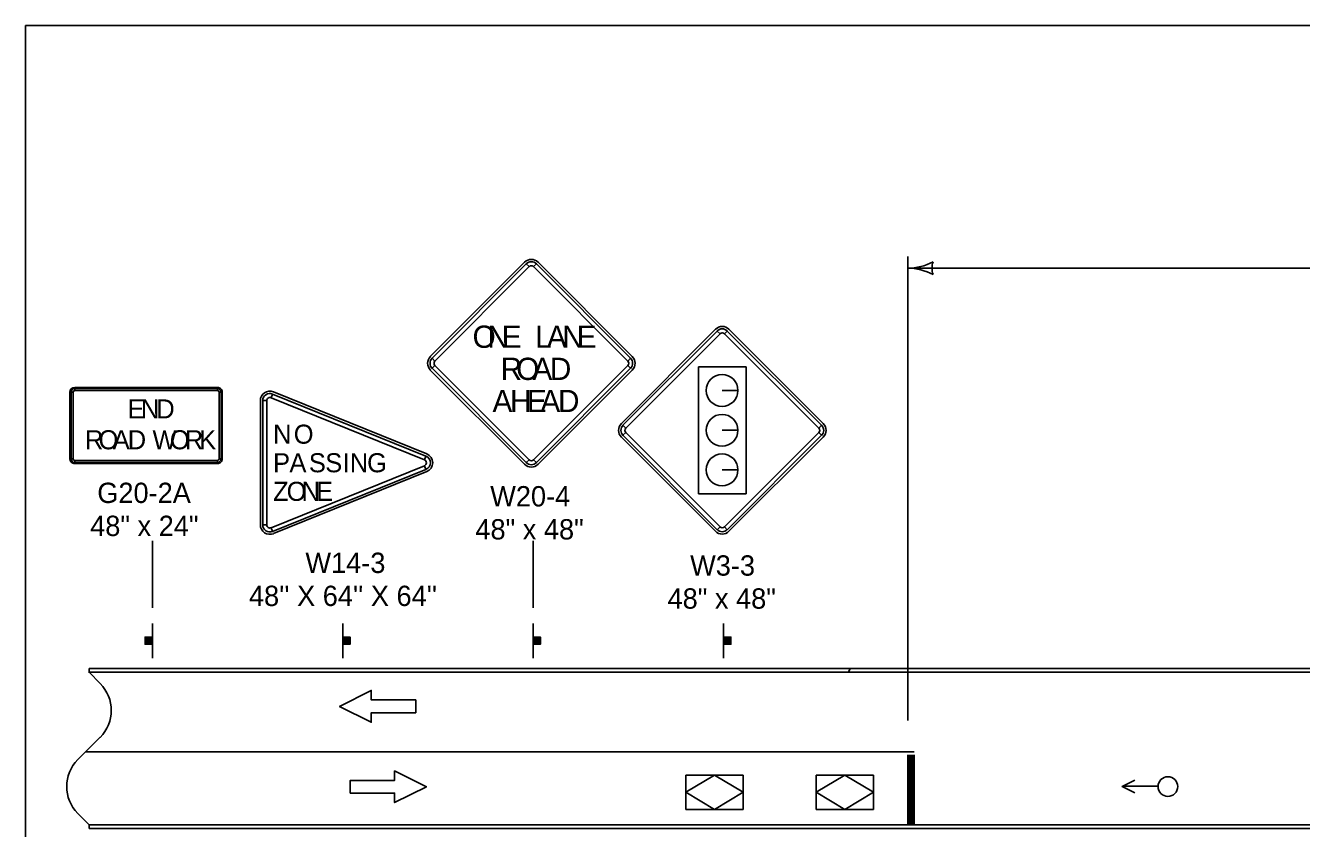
# Model space of a CAD drawing. Extents: x -2134934 to -2119606, y -2139046 to -2137036.
# Drawn here: x -2134934 to -2133929, y -2137668 to -2137036 of the extents above; entities that cross this region are included whole.
import ezdxf

# ---------------------------------------------------------------- set-up
doc = ezdxf.new("R2010")
doc.units = 0
for name, color, linetype in [('Default', 7, 'Continuous'), ('dsnCellElements', 7, 'Continuous'), ('dsnStdLabel', 7, 'Continuous'), ('dsnStdLineWork', 7, 'Continuous'), ('Level 2', 7, 'Continuous'), ('Level 4', 7, 'Continuous')]:
    doc.layers.add(name, color=color, linetype=linetype)

msp = doc.modelspace()

# ---------------------------------------------------------------- linework, layer by layer
at = {"layer": 'Default'}
msp.add_lwpolyline([(-2134934.4, -2137035.9), (-2131799.4, -2137035.9), (-2131799.4, -2139045.9), (-2134934.4, -2139045.9)], close=True, dxfattribs=at)
at = {"layer": 'dsnCellElements'}
for centre, radius, start, end in [((-2134239.4, -2137184.5), 42.5, 270, 298.0725), ((-2134203.8, -2137227), 16.4, 162.2666, 197.7334), ((-2134239.4, -2137269.5), 42.5, 61.9275, 90)]:
    msp.add_arc(centre, radius, start, end, dxfattribs=at)
at = {"layer": 'dsnStdLabel'}
for p, q in [((-2134541.2, -2137222.3), (-2134615.5, -2137296.6)), ((-2134456.4, -2137296.6), (-2134530.6, -2137222.3)), ((-2134539.9, -2137223.6), (-2134537.7, -2137225.8)), ((-2134534.1, -2137225.8), (-2134531.9, -2137223.6)), ((-2134390.8, -2137275.1), (-2134465, -2137349.4)), ((-2134389.4, -2137276.5), (-2134387.2, -2137278.7)), ((-2134383.7, -2137278.7), (-2134381.5, -2137276.5)), ((-2134305.9, -2137349.4), (-2134380.2, -2137275.1)), ((-2134611.9, -2137300.1), (-2134614.1, -2137297.9)), ((-2134614.1, -2137305.8), (-2134611.9, -2137303.6)), ((-2134457.7, -2137297.9), (-2134459.9, -2137300.1)), ((-2134459.9, -2137303.6), (-2134457.7, -2137305.8)), ((-2134615.5, -2137307.2), (-2134541.2, -2137381.4)), ((-2134530.6, -2137381.4), (-2134456.4, -2137307.2)), ((-2134783.2, -2137320.9), (-2134895.7, -2137320.9)), ((-2134895.7, -2137323.4), (-2134895.7, -2137321.8)), ((-2134783.2, -2137321.8), (-2134783.2, -2137323.4)), ((-2134373.1, -2137323.3), (-2134385.6, -2137323.3)), ((-2134385.6, -2137323.3), (-2134373.1, -2137323.3)), ((-2134899.4, -2137324.6), (-2134899.4, -2137377.1)), ((-2134898.5, -2137324.6), (-2134896.9, -2137324.6)), ((-2134781.9, -2137324.6), (-2134780.4, -2137324.6)), ((-2134779.4, -2137377.1), (-2134779.4, -2137324.6)), ((-2134749.4, -2137331.3), (-2134749.4, -2137429.1)), ((-2134747.5, -2137331.3), (-2134744.4, -2137331.3)), ((-2134741, -2137329), (-2134739.8, -2137326.1)), ((-2134618.3, -2137373.2), (-2134739.1, -2137324.4)), ((-2134461.5, -2137352.9), (-2134463.7, -2137350.7)), ((-2134307.2, -2137350.7), (-2134309.5, -2137352.9)), ((-2134465, -2137360), (-2134390.8, -2137434.2)), ((-2134463.7, -2137358.6), (-2134461.5, -2137356.4)), ((-2134373.1, -2137354.6), (-2134385.6, -2137354.6)), ((-2134385.6, -2137354.6), (-2134373.1, -2137354.6)), ((-2134380.2, -2137434.2), (-2134305.9, -2137360)), ((-2134309.5, -2137356.4), (-2134307.2, -2137358.6)), ((-2134896.9, -2137377.1), (-2134898.5, -2137377.1)), ((-2134895.7, -2137379.9), (-2134895.7, -2137378.4)), ((-2134895.7, -2137380.9), (-2134783.2, -2137380.9)), ((-2134783.2, -2137378.4), (-2134783.2, -2137379.9)), ((-2134780.4, -2137377.1), (-2134781.9, -2137377.1)), ((-2134619, -2137375), (-2134620.1, -2137377.9)), ((-2134620.1, -2137382.5), (-2134619, -2137385.4)), ((-2134537.7, -2137377.9), (-2134539.9, -2137380.1)), ((-2134531.9, -2137380.1), (-2134534.1, -2137377.9)), ((-2134739.1, -2137436), (-2134618.3, -2137387.2)), ((-2134373.1, -2137385.8), (-2134385.6, -2137385.8)), ((-2134385.6, -2137385.8), (-2134373.1, -2137385.8)), ((-2134744.4, -2137429.1), (-2134747.5, -2137429.1)), ((-2134739.8, -2137434.3), (-2134741, -2137431.4)), ((-2134387.2, -2137430.7), (-2134389.4, -2137432.9)), ((-2134381.5, -2137432.9), (-2134383.7, -2137430.7))]:
    msp.add_line(p, q, dxfattribs=at)
for points in [[(-2134539.9, -2137223.6), (-2134614.1, -2137297.9), (-2134611.9, -2137300.1), (-2134537.7, -2137225.8), (-2134539.9, -2137223.6)], [(-2134457.7, -2137297.9), (-2134531.9, -2137223.6), (-2134534.1, -2137225.8), (-2134459.9, -2137300.1), (-2134457.7, -2137297.9)], [(-2134389.4, -2137276.5), (-2134463.7, -2137350.7), (-2134461.5, -2137352.9), (-2134387.2, -2137278.7), (-2134389.4, -2137276.5)], [(-2134307.2, -2137350.7), (-2134381.5, -2137276.5), (-2134383.7, -2137278.7), (-2134309.5, -2137352.9), (-2134307.2, -2137350.7)], [(-2134614.1, -2137305.8), (-2134539.9, -2137380.1), (-2134537.7, -2137377.9), (-2134611.9, -2137303.6), (-2134614.1, -2137305.8)], [(-2134531.9, -2137380.1), (-2134457.7, -2137305.8), (-2134459.9, -2137303.6), (-2134534.1, -2137377.9), (-2134531.9, -2137380.1)], [(-2134366.7, -2137304.7), (-2134404.2, -2137304.7), (-2134404.2, -2137404.6), (-2134366.7, -2137404.6), (-2134366.7, -2137304.7)], [(-2134783.2, -2137321.8), (-2134895.7, -2137321.8), (-2134895.7, -2137323.4), (-2134783.2, -2137323.4), (-2134783.2, -2137321.8)], [(-2134898.5, -2137324.6), (-2134898.5, -2137377.1), (-2134896.9, -2137377.1), (-2134896.9, -2137324.6), (-2134898.5, -2137324.6)], [(-2134780.4, -2137377.1), (-2134780.4, -2137324.6), (-2134781.9, -2137324.6), (-2134781.9, -2137377.1), (-2134780.4, -2137377.1)], [(-2134747.5, -2137331.3), (-2134747.5, -2137429.1), (-2134744.4, -2137429.1), (-2134744.4, -2137331.3), (-2134747.5, -2137331.3)], [(-2134619, -2137375), (-2134739.8, -2137326.1), (-2134741, -2137329), (-2134620.1, -2137377.9), (-2134619, -2137375)], [(-2134463.7, -2137358.6), (-2134389.4, -2137432.9), (-2134387.2, -2137430.7), (-2134461.5, -2137356.4), (-2134463.7, -2137358.6)], [(-2134381.5, -2137432.9), (-2134307.2, -2137358.6), (-2134309.5, -2137356.4), (-2134383.7, -2137430.7), (-2134381.5, -2137432.9)], [(-2134895.7, -2137379.9), (-2134783.2, -2137379.9), (-2134783.2, -2137378.4), (-2134895.7, -2137378.4), (-2134895.7, -2137379.9)], [(-2134739.8, -2137434.3), (-2134619, -2137385.4), (-2134620.1, -2137382.5), (-2134741, -2137431.4), (-2134739.8, -2137434.3)]]:
    msp.add_lwpolyline(points, close=True, dxfattribs=at)
for centre in [(-2134385.6, -2137323.3), (-2134385.6, -2137354.6), (-2134385.6, -2137385.8)]:
    msp.add_circle(centre, 12.5, dxfattribs=at)
for centre, radius, start, end in [((-2134535.9, -2137227.6), 7.5, 45, 134.9997), ((-2134535.9, -2137227.6), 5.62, 45, 134.9997), ((-2134535.9, -2137227.6), 2.5, 45, 134.9997), ((-2134385.5, -2137280.4), 7.5, 45, 134.9997), ((-2134385.5, -2137280.4), 5.62, 45, 134.9997), ((-2134385.5, -2137280.4), 2.5, 45, 134.9997), ((-2134610.1, -2137301.9), 7.5, 134.9997, 225), ((-2134610.1, -2137301.9), 5.62, 134.9997, 225), ((-2134610.1, -2137301.9), 2.5, 134.9997, 225), ((-2134461.7, -2137301.9), 2.5, 315.0002, 44.9998), ((-2134461.7, -2137301.9), 5.62, 315.0002, 44.9998), ((-2134461.7, -2137301.9), 7.5, 315.0002, 44.9998), ((-2134895.7, -2137324.6), 3.75, 90.0002, 179.9998), ((-2134895.7, -2137324.6), 2.81, 90.0002, 179.9998), ((-2134895.7, -2137324.6), 1.25, 90.0002, 179.9998), ((-2134783.2, -2137324.6), 3.75, 0, 90.0002), ((-2134783.2, -2137324.6), 2.81, 0, 90.0002), ((-2134783.2, -2137324.6), 1.25, 0, 90.0002), ((-2134741.9, -2137331.3), 7.5, 67.9757, 179.9998), ((-2134741.9, -2137331.3), 5.62, 67.9757, 179.9998), ((-2134741.9, -2137331.3), 2.5, 67.9757, 179.9998), ((-2134459.7, -2137354.7), 7.5, 134.9997, 225), ((-2134459.7, -2137354.7), 5.62, 134.9997, 225), ((-2134459.7, -2137354.7), 2.5, 134.9997, 225), ((-2134311.2, -2137354.7), 2.5, 315.0002, 44.9998), ((-2134311.2, -2137354.7), 5.62, 315.0002, 44.9998), ((-2134311.2, -2137354.7), 7.5, 315.0002, 44.9998), ((-2134621.1, -2137380.2), 7.5, 292.0246, 67.976), ((-2134895.7, -2137377.1), 3.75, 179.9998, 270.0001), ((-2134895.7, -2137377.1), 2.81, 179.9998, 270.0001), ((-2134895.7, -2137377.1), 1.25, 179.9998, 270.0001), ((-2134783.2, -2137377.1), 3.75, 270.0001, 0.0003), ((-2134783.2, -2137377.1), 2.81, 270.0001, 0.0003), ((-2134783.2, -2137377.1), 1.25, 270.0001, 0.0003), ((-2134621.1, -2137380.2), 2.5, 292.0246, 67.9754), ((-2134621.1, -2137380.2), 5.62, 292.0246, 67.9754), ((-2134535.9, -2137376.1), 7.5, 225, 315.0002), ((-2134535.9, -2137376.1), 5.62, 225, 315.0002), ((-2134535.9, -2137376.1), 2.5, 225, 315.0002), ((-2134741.9, -2137429.1), 7.5, 179.9998, 292.0246), ((-2134741.9, -2137429.1), 5.62, 179.9998, 292.0246), ((-2134741.9, -2137429.1), 2.5, 179.9998, 292.0246), ((-2134385.5, -2137428.9), 7.5, 225, 315.0002), ((-2134385.5, -2137428.9), 5.62, 225, 315.0002), ((-2134385.5, -2137428.9), 2.5, 225, 315.0002)]:
    msp.add_arc(centre, radius, start, end, dxfattribs=at)
at = {"layer": 'dsnStdLineWork'}
for p, q in [((-2134884.4, -2137542.2), (-2134884.4, -2137545.2)), ((-2134884.4, -2137542.2), (-2134884.4, -2137545.2)), ((-2134284.7, -2137542.2), (-2134884.4, -2137542.2)), ((-2134284.7, -2137542.2), (-2134285.9, -2137545.2)), ((-2134285.9, -2137545.2), (-2134284.7, -2137542.2)), ((-2134239.4, -2137542.2), (-2134284.7, -2137542.2)), ((-2133766.5, -2137542.2), (-2134239.4, -2137542.2)), ((-2134239.4, -2137542.2), (-2134239.4, -2137545.2)), ((-2134239.4, -2137545.2), (-2134239.4, -2137542.2)), ((-2134884.4, -2137545.2), (-2134285.9, -2137545.2)), ((-2134285.9, -2137545.2), (-2134239.4, -2137545.2)), ((-2134239.4, -2137545.2), (-2133764.3, -2137545.2)), ((-2134234.4, -2137607.7), (-2134886.9, -2137607.7)), ((-2134884.4, -2137665.2), (-2133384.4, -2137665.2)), ((-2134884.4, -2137665.2), (-2133384.4, -2137665.2)), ((-2134884.4, -2137668.2), (-2134884.4, -2137665.2)), ((-2134239.4, -2137665.2), (-2134884.4, -2137665.2)), ((-2134884.4, -2137665.2), (-2134884.4, -2137668.2)), ((-2134238.4, -2137665.2), (-2134239.4, -2137665.2)), ((-2134237.4, -2137665.2), (-2134238.4, -2137665.2)), ((-2134236.4, -2137665.2), (-2134237.4, -2137665.2)), ((-2133384.4, -2137665.2), (-2134234.4, -2137665.2)), ((-2134884.4, -2137668.2), (-2133384.4, -2137668.2)), ((-2134884.4, -2137668.2), (-2133384.4, -2137668.2))]:
    msp.add_line(p, q, dxfattribs=at)
for points in [[(-2134884.4, -2137542.2), (-2133574.4, -2137542.2)], [(-2134884.9, -2137545.2), (-2133574.9, -2137545.2)], [(-2134884.4, -2137545.2), (-2133574.4, -2137545.2)], [(-2134234.4, -2137665.2), (-2134235.4, -2137665.2), (-2134236.4, -2137665.2)]]:
    msp.add_lwpolyline(points, dxfattribs=at)
at = {"layer": 'Level 2'}
for p, q in [((-2134239.4, -2137583.2), (-2134239.4, -2137217.7)), ((-2134239.4, -2137227), (-2133580, -2137227)), ((-2134834.4, -2137494.5), (-2134834.4, -2137441.6)), ((-2134534.4, -2137494.5), (-2134534.4, -2137441.6)), ((-2134834.4, -2137506.7), (-2134834.4, -2137534.2)), ((-2134684.4, -2137506.7), (-2134684.4, -2137534.2)), ((-2134534.4, -2137506.7), (-2134534.4, -2137534.2)), ((-2134384.4, -2137506.7), (-2134384.4, -2137534.2)), ((-2134839.8, -2137517.5), (-2134839.8, -2137523.1)), ((-2134839.4, -2137523.1), (-2134839.4, -2137517.5)), ((-2134839.2, -2137517.5), (-2134839.2, -2137523.1)), ((-2134838.9, -2137523.1), (-2134838.9, -2137517.5)), ((-2134838.7, -2137517.5), (-2134838.7, -2137523.1)), ((-2134838.3, -2137523.1), (-2134838.2, -2137517.5)), ((-2134838, -2137517.5), (-2134838, -2137523.1)), ((-2134837.6, -2137523.1), (-2134837.6, -2137517.5)), ((-2134837.2, -2137517.5), (-2134837.2, -2137523.1)), ((-2134836.9, -2137523.1), (-2134836.9, -2137517.5)), ((-2134836.7, -2137517.5), (-2134836.7, -2137523.1)), ((-2134836.4, -2137523.1), (-2134836.4, -2137517.5)), ((-2134836.1, -2137517.5), (-2134836.1, -2137523.1)), ((-2134835.9, -2137523.1), (-2134835.9, -2137517.5)), ((-2134835.7, -2137517.5), (-2134835.7, -2137523.1)), ((-2134835.4, -2137523.1), (-2134835.4, -2137517.5)), ((-2134835.1, -2137517.5), (-2134835.1, -2137523.1)), ((-2134834.9, -2137523.1), (-2134834.9, -2137517.5)), ((-2134684, -2137523.1), (-2134684, -2137517.5)), ((-2134683.7, -2137517.5), (-2134683.7, -2137523.1)), ((-2134683.5, -2137523.1), (-2134683.5, -2137517.5)), ((-2134683.2, -2137517.5), (-2134683.2, -2137523.1)), ((-2134683, -2137523.1), (-2134683, -2137517.5)), ((-2134682.8, -2137517.5), (-2134682.8, -2137523.1)), ((-2134682.5, -2137523.1), (-2134682.5, -2137517.5)), ((-2134682.2, -2137517.5), (-2134682.2, -2137523.1)), ((-2134682, -2137523.1), (-2134682, -2137517.5)), ((-2134681.6, -2137517.5), (-2134681.6, -2137523.1)), ((-2134681.3, -2137523.1), (-2134681.3, -2137517.5)), ((-2134680.8, -2137517.5), (-2134680.8, -2137523.1)), ((-2134680.6, -2137523.1), (-2134680.6, -2137517.5)), ((-2134680.2, -2137517.5), (-2134680.2, -2137523.1)), ((-2134680, -2137523.1), (-2134680, -2137517.5)), ((-2134679.7, -2137517.5), (-2134679.7, -2137523.1)), ((-2134679.4, -2137523.1), (-2134679.4, -2137517.5)), ((-2134679.1, -2137517.5), (-2134679.1, -2137523.1)), ((-2134534, -2137523.1), (-2134534, -2137517.5)), ((-2134533.7, -2137517.5), (-2134533.7, -2137523.1)), ((-2134533.5, -2137523.1), (-2134533.5, -2137517.5)), ((-2134533.2, -2137517.5), (-2134533.2, -2137523.1)), ((-2134533, -2137523.1), (-2134533, -2137517.5)), ((-2134532.8, -2137517.5), (-2134532.8, -2137523.1)), ((-2134532.5, -2137523.1), (-2134532.5, -2137517.5)), ((-2134532.2, -2137517.5), (-2134532.2, -2137523.1)), ((-2134532, -2137523.1), (-2134532, -2137517.5)), ((-2134531.6, -2137517.5), (-2134531.6, -2137523.1)), ((-2134531.3, -2137523.1), (-2134531.3, -2137517.5)), ((-2134530.8, -2137517.5), (-2134530.8, -2137523.1)), ((-2134530.6, -2137523.1), (-2134530.6, -2137517.5)), ((-2134530.2, -2137517.5), (-2134530.2, -2137523.1)), ((-2134530, -2137523.1), (-2134530, -2137517.5)), ((-2134529.7, -2137517.5), (-2134529.7, -2137523.1)), ((-2134529.4, -2137523.1), (-2134529.4, -2137517.5)), ((-2134529.1, -2137517.5), (-2134529.1, -2137523.1)), ((-2134384, -2137523.1), (-2134384, -2137517.5)), ((-2134383.7, -2137517.5), (-2134383.7, -2137523.1)), ((-2134383.5, -2137523.1), (-2134383.5, -2137517.5)), ((-2134383.2, -2137517.5), (-2134383.2, -2137523.1)), ((-2134383, -2137523.1), (-2134383, -2137517.5)), ((-2134382.8, -2137517.5), (-2134382.8, -2137523.1)), ((-2134382.5, -2137523.1), (-2134382.5, -2137517.5)), ((-2134382.2, -2137517.5), (-2134382.2, -2137523.1)), ((-2134382, -2137523.1), (-2134382, -2137517.5)), ((-2134381.6, -2137517.5), (-2134381.6, -2137523.1)), ((-2134381.3, -2137523.1), (-2134381.3, -2137517.5)), ((-2134380.8, -2137517.5), (-2134380.8, -2137523.1)), ((-2134380.6, -2137523.1), (-2134380.6, -2137517.5)), ((-2134380.2, -2137517.5), (-2134380.2, -2137523.1)), ((-2134380, -2137523.1), (-2134380, -2137517.5)), ((-2134379.7, -2137517.5), (-2134379.7, -2137523.1)), ((-2134379.4, -2137523.1), (-2134379.4, -2137517.5)), ((-2134379.1, -2137517.5), (-2134379.1, -2137523.1)), ((-2134875.7, -2137553.9), (-2134884.4, -2137545.2)), ((-2133574.4, -2137545.2), (-2134884.4, -2137545.2)), ((-2134884.4, -2137545.2), (-2134875.7, -2137553.9)), ((-2134893.2, -2137613.9), (-2134875.7, -2137596.4)), ((-2134875.7, -2137596.4), (-2134893.2, -2137613.9)), ((-2134239.4, -2137665.2), (-2134239.4, -2137610.2)), ((-2134238.4, -2137665.2), (-2134238.4, -2137610.2)), ((-2134237.4, -2137665.2), (-2134237.4, -2137610.2)), ((-2134236.4, -2137665.2), (-2134236.4, -2137610.2)), ((-2134235.4, -2137665.2), (-2134235.4, -2137610.2)), ((-2134234.4, -2137665.2), (-2134234.4, -2137610.2)), ((-2134414.1, -2137653.1), (-2134414.1, -2137626.1)), ((-2134414.1, -2137626.1), (-2134369.1, -2137626.1)), ((-2134414.1, -2137653.1), (-2134414.1, -2137626.1)), ((-2134414.1, -2137626.1), (-2134369.1, -2137626.1)), ((-2134369.1, -2137626.1), (-2134414.1, -2137626.1)), ((-2134414.1, -2137626.1), (-2134414.1, -2137653.1)), ((-2134369.1, -2137653.1), (-2134369.1, -2137626.1)), ((-2134369.1, -2137626.1), (-2134369.1, -2137653.1)), ((-2134369.1, -2137653.1), (-2134369.1, -2137626.1)), ((-2134311.4, -2137653.1), (-2134311.4, -2137626.1)), ((-2134311.4, -2137626.1), (-2134266.4, -2137626.1)), ((-2134311.4, -2137653.1), (-2134311.4, -2137626.1)), ((-2134311.4, -2137626.1), (-2134266.4, -2137626.1)), ((-2134266.4, -2137626.1), (-2134311.4, -2137626.1)), ((-2134311.4, -2137626.1), (-2134311.4, -2137653.1)), ((-2134266.4, -2137653.1), (-2134266.4, -2137626.1)), ((-2134266.4, -2137626.1), (-2134266.4, -2137653.1)), ((-2134266.4, -2137653.1), (-2134266.4, -2137626.1)), ((-2134042.2, -2137634.8), (-2134070.1, -2137634.8)), ((-2134414.1, -2137653.1), (-2134369.1, -2137653.1)), ((-2134369.1, -2137653.1), (-2134414.1, -2137653.1)), ((-2134414.1, -2137653.1), (-2134369.1, -2137653.1)), ((-2134311.4, -2137653.1), (-2134266.4, -2137653.1)), ((-2134266.4, -2137653.1), (-2134311.4, -2137653.1)), ((-2134311.4, -2137653.1), (-2134266.4, -2137653.1)), ((-2134884.4, -2137665.2), (-2134893.2, -2137656.4)), ((-2134893.2, -2137656.4), (-2134884.4, -2137665.2)), ((-2134884.4, -2137665.2), (-2133384.4, -2137665.2))]:
    msp.add_line(p, q, dxfattribs=at)
for points in [[(-2134834.5, -2137523.1), (-2134834.5, -2137517.5), (-2134840.2, -2137517.5), (-2134840.2, -2137523.1)], [(-2134684.3, -2137523.1), (-2134684.3, -2137517.5), (-2134678.7, -2137517.5), (-2134678.7, -2137523.1)], [(-2134534.3, -2137523.1), (-2134534.3, -2137517.5), (-2134528.7, -2137517.5), (-2134528.7, -2137523.1)], [(-2134384.3, -2137523.1), (-2134384.3, -2137517.5), (-2134378.7, -2137517.5), (-2134378.7, -2137523.1)], [(-2134627, -2137577), (-2134627, -2137567), (-2134662, -2137567), (-2134662, -2137559.5), (-2134687, -2137572), (-2134662, -2137584.5), (-2134662, -2137577)], [(-2134678.6, -2137630.3), (-2134678.6, -2137640.3), (-2134643.6, -2137640.3), (-2134643.6, -2137647.8), (-2134618.6, -2137635.3), (-2134643.6, -2137622.8), (-2134643.6, -2137630.3)]]:
    msp.add_lwpolyline(points, close=True, dxfattribs=at)
for points in [[(-2134662, -2137577), (-2134662, -2137584.5), (-2134687, -2137572), (-2134662, -2137559.5), (-2134662, -2137567), (-2134627, -2137567), (-2134627, -2137577), (-2134662, -2137577)], [(-2134643.6, -2137630.3), (-2134643.6, -2137622.8), (-2134618.6, -2137635.3), (-2134643.6, -2137647.8), (-2134643.6, -2137640.3), (-2134678.6, -2137640.3), (-2134678.6, -2137630.3), (-2134643.6, -2137630.3)], [(-2134060.5, -2137630), (-2134070.5, -2137635), (-2134060.5, -2137640)]]:
    msp.add_lwpolyline(points, dxfattribs=at)
msp.add_circle((-2134034.4, -2137635.2), 7.74, dxfattribs=at)
for centre, start, end in [((-2134896.9, -2137575.2), 315, 45), ((-2134896.9, -2137575.2), 315, 45), ((-2134872, -2137635.2), 135, 225), ((-2134872, -2137635.2), 135, 225)]:
    msp.add_arc(centre, 30, start, end, dxfattribs=at)
at = {"layer": 'Level 4'}
for points in [[(-2134414.1, -2137639.6), (-2134391.6, -2137626.1), (-2134369.1, -2137639.6), (-2134391.6, -2137653.1)], [(-2134311.4, -2137639.6), (-2134288.9, -2137626.1), (-2134266.4, -2137639.6), (-2134288.9, -2137653.1)]]:
    msp.add_lwpolyline(points, close=True, dxfattribs=at)

# ---------------------------------------------------------------- texts
at = {"layer": 'dsnStdLabel'}
for s, height, p in [('O', 17.5, (-2134582.2, -2137289.7)), ('N', 17.5, (-2134570.4, -2137289.7)), ('E', 17.5, (-2134559.2, -2137289.7)), ('L', 17.5, (-2134532.9, -2137289.7)), ('A', 17.5, (-2134523.7, -2137289.7)), ('N', 17.5, (-2134511.5, -2137289.7)), ('E', 17.5, (-2134500.2, -2137289.7)), ('R', 17.5, (-2134560.1, -2137315)), ('O', 17.5, (-2134547.8, -2137315)), ('A', 17.5, (-2134535, -2137315)), ('D', 17.5, (-2134521.3, -2137315)), ('A', 17.5, (-2134566.5, -2137340.3)), ('H', 17.5, (-2134552.7, -2137340.3)), ('E', 17.5, (-2134539.4, -2137340.3)), ('A', 17.5, (-2134528.7, -2137340.3)), ('D', 17.5, (-2134514.9, -2137340.3)), ('E', 15, (-2134854.1, -2137345.3)), ('N', 15, (-2134843.5, -2137345.3)), ('D', 15, (-2134831.4, -2137345.3)), ('N', 15, (-2134739.4, -2137365.2)), ('O', 15, (-2134723.1, -2137365.2)), ('R', 15, (-2134887.6, -2137369.6)), ('O', 15, (-2134876.9, -2137369.6)), ('A', 15, (-2134865.7, -2137369.6)), ('D', 15, (-2134853.9, -2137369.6)), ('W', 15, (-2134834.4, -2137369.6)), ('O', 15, (-2134820.7, -2137369.6)), ('R', 15, (-2134808.9, -2137369.6)), ('K', 15, (-2134797.6, -2137369.6)), ('P', 15, (-2134739.4, -2137387.7)), ('A', 15, (-2134726.5, -2137387.7)), ('S', 15, (-2134711.2, -2137387.7)), ('S', 15, (-2134698.3, -2137387.7)), ('I', 15, (-2134684.7, -2137387.7)), ('N', 15, (-2134678.9, -2137387.7)), ('G', 15, (-2134665.3, -2137387.7)), ('G20-2A', 16, (-2134877.9, -2137411.9)), ('Z', 15, (-2134739.4, -2137410.2)), ('O', 15, (-2134728.7, -2137410.2)), ('N', 15, (-2134716.9, -2137410.2)), ('E', 15, (-2134705.5, -2137410.2)), ('W20-4', 16, (-2134568.3, -2137414.6)), ('48" x 24"', 16, (-2134883.5, -2137437.9)), ('48" x 48"', 16, (-2134580, -2137440.6)), ('W14-3', 16, (-2134713.9, -2137467)), ('W3-3', 16, (-2134410.8, -2137469.1)), ("48'' X 64'' X 64''", 16, (-2134758.4, -2137493)), ('48" x 48"', 16, (-2134428.6, -2137495.1))]:
    msp.add_text(s, height=height, dxfattribs=at).set_placement(p)

doc.saveas('drawing.dxf')
